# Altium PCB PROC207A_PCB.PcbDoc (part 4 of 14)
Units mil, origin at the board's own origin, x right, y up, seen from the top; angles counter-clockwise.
Board outline 4094.49 x 3724.79 mil, 8 copper layers (Top Layer, L2_GND1, L3_SIG1, L4_PWR1, L5_PWR2, L6_SIG2, L7_GND2, Bottom Layer), stack 58.1 mil thick; 584 components, 399 nets, 8440 pads, 5258 vias.
Unrouted connection lines stored in the file: 9.
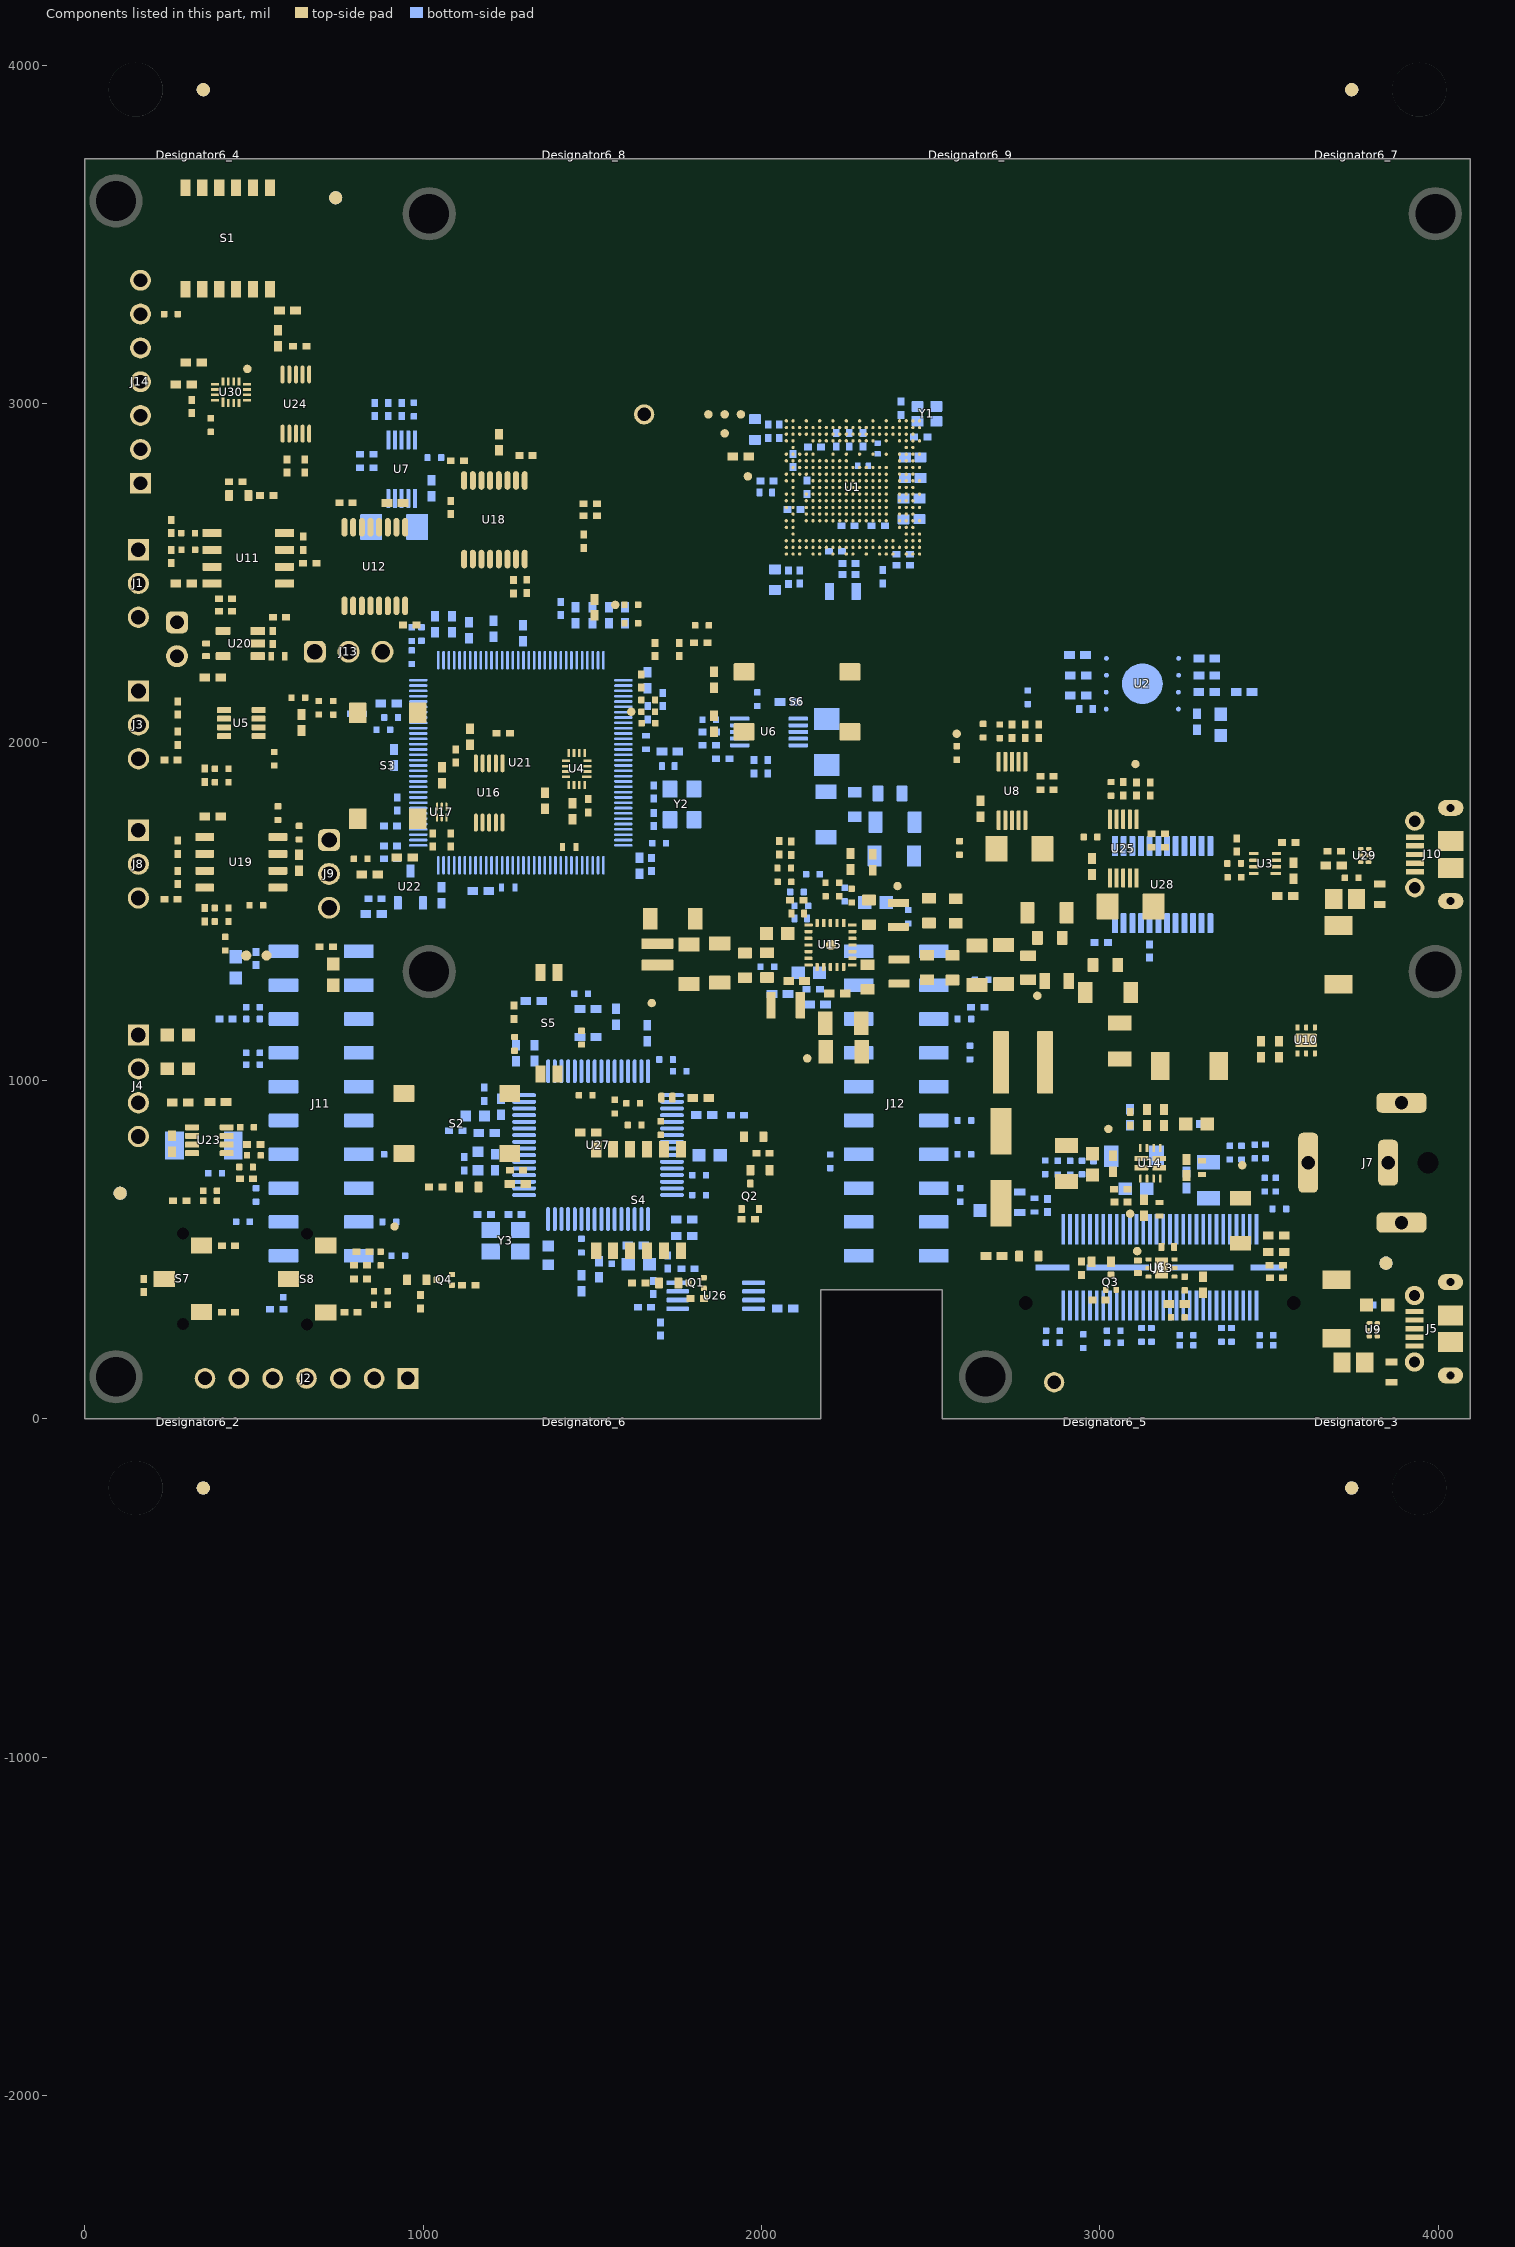
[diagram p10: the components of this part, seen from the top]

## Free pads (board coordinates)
  round 1 on Mech13: 0(1166.41,3201.26)
  round 10 on Mech16: 1(279.42,-2261) 1(279.42,-2261) 1(279.42,3039) 1(279.42,3039) 1(726.33,318.51) 1(740.31,318.51) 1(2054.9,976.3) 1(2066.33,976.3) 1(2509,314.72) 1(2525.34,314.72) 1(2695.25,961) 1(2707.26,961) 1(2839.79,1070.45) 1(2839.79,1745.45) 1(2849.98,1070.45) 1(2849.98,1745.45) 1(3035.32,-2261) 1(3035.32,-2261) 1(3035.32,3039) 1(3035.32,3039) 1(3035.49,821.54) 1(3035.49,1215.24) 1(3035.49,1496.54) 1(3035.49,1890.24)
  round 7.87 on Mech16: 1(316.04,-124.6) 1(316.69,-99.37) 1(319.14,2898.86) 1(319.79,2924.1) 1(331.77,-168.17) 1(332.54,-59.62) 1(334.86,2855.3) 1(335.64,2963.84) 1(343.86,-182.93) 1(346.96,2840.54) 1(349.31,-40.97) 1(352.41,2982.5) 1(381.7,-206.31) 1(381.7,-22.63) 1(384.8,2817.15) 1(384.8,3000.84) 1(397.96,-18.73) 1(401.06,3004.74) 1(406.95,-211.13) 1(410.05,2812.34) 1(436.96,-20.85) 1(440.05,3002.62) 1(449.89,-203.69) 1(451.64,-26) 1(452.98,2819.77) 1(454.73,2997.46) 1(467.16,-194.25) 1(470.26,2829.22) 1(483.26,-48.59) 1(486.36,2974.87) 1(492.87,-168.17) 1(495.97,2855.3) 1(496.16,-66.06) 1(499.26,2957.4) 1(501.54,-152.04) 1(504.64,2871.43) 1(507.94,-99.37) 1(509.01,-119.3) 1(511.04,2924.1) 1(512.11,2904.16) 1(575.75,-153.03) 1(575.75,-113.66) 1(598.27,432) 1(598.27,432) 1(598.27,446.17) 1(598.27,1417.82) 1(598.27,1432) 1(598.27,1432) 1(606.48,31.99) 1(606.48,146.17) 1(606.48,217.82) 1(606.48,332) 1(606.48,332) 1(607.03,32) 1(650.56,-168.77) 1(650.56,-113.66) 1(706.48,320.97) 1(706.48,320.97) 1(706.48,332) 1(706.48,332) 1(706.48,332) 1(707.03,32) 1(707.03,32) 1(707.03,46.17) 1(746.59,320.97) 1(746.59,320.97) 1(746.59,332) 1(746.59,332) 1(749.46,-61.66) 1(749.46,-53.78) 1(749.46,-163.03) 1(749.46,-143.35) 1(798.27,432) 1(798.27,432) 1(798.27,446.17) 1(798.27,1417.82) 1(798.27,1432) 1(798.27,1432) 1(834.11,-158.11) 1(834.11,-150.24) 1(834.11,-61.66) 1(834.11,-53.78) 1(861.88,23.62) 1(861.88,108.27) 1(868.88,173.68) 1(868.88,258.32) 1(869.75,23.62) 1(869.75,108.27) 1(876.75,173.68) 1(876.75,258.32) 1(901.19,1290.09) 1(901.19,1290.09) 1(901.19,1420.01) 1(901.19,1420.01) 1(945.62,-302.27) 1(945.62,-217.62) 1(949.62,-121.27) 1(949.62,-36.62) 1(951.45,23.62) 1(953.49,-302.27) 1(953.49,-217.62) 1(957.49,-121.27) 1(957.49,-36.62) 1(958.34,108.27) 1(958.45,173.68) 1(965.34,258.32) 1(966.21,108.27) 1(971.13,23.62) 1(973.21,258.32) 1(978.13,173.68) 1(987.8,1290.09) 1(987.8,1420.01) 1(1035.19,-302.27) 1(1039.19,-121.27) 1(1042.08,-217.62) 1(1046.08,-36.62) 1(1049.95,-217.62) 1(1053.95,-36.62) 1(1054.87,-302.27) 1(1058.87,-121.27) 1(1063.38,858.87) 1(1063.38,878.56) 1(1063.38,878.56) 1(1082.75,536.38) 1(1082.75,578.71) 1(1083.77,1290.09) 1(1083.77,1420.01) 1(1094.88,878.56) 1(1150,878.56) 1(1170.39,1290.09) 1(1170.39,1290.09) 1(1170.39,1420.01) 1(1170.39,1420.01) 1(1181.49,858.87) 1(1181.49,878.56) 1(1181.49,878.56) 1(1202.83,496.03) 1(1202.83,578.71) 1(1217.33,-293.68) 1(1222.25,-378.33) 1(1230.12,-378.33) 1(1237.01,-293.68) 1(1318.71,-378.33) 1(1318.71,-293.68) 1(1326.58,-378.33) 1(1326.58,-293.68) 1(1353.98,764.89) 1(1353.98,780.64) 1(1353.98,796.38) 1(1353.98,812.13) 1(1353.98,827.88) 1(1353.98,843.63) 1(1353.98,859.38) 1(1353.98,875.12) 1(1353.98,890.87) 1(1353.98,906.62) 1(1353.98,922.37) 1(1353.98,938.12) 1(1353.98,953.86) 1(1353.98,969.61) 1(1353.98,985.36) 1(1353.98,1001.11) 1(1353.98,1016.86) 1(1353.98,1032.6) 1(1353.98,1048.35) 1(1353.98,1064.1) 1(1353.98,1079.85) 1(1353.98,1095.6) 1(1353.98,1111.34) 1(1353.98,1127.09) 1(1353.98,1142.84) 1(1353.98,1158.59) 1(1353.98,1174.34) 1(1353.98,1190.08) 1(1353.98,1205.83) 1(1353.98,1221.58) 1(1353.98,1237.33) 1(1353.98,1253.08) 1(1401.22,764.89) 1(1401.22,780.64) 1(1401.22,796.38) 1(1401.22,812.13) 1(1401.22,827.88) 1(1401.22,843.63) 1(1401.22,859.38) 1(1401.22,875.12) 1(1401.22,890.87) 1(1401.22,906.62) 1(1401.22,922.37) 1(1401.22,938.12) 1(1401.22,953.86) 1(1401.22,969.61) 1(1401.22,985.36) 1(1401.22,1001.11) 1(1401.22,1016.86) 1(1401.22,1032.6) 1(1401.22,1048.35) 1(1401.22,1064.1) 1(1401.22,1079.85) 1(1401.22,1095.6) 1(1401.22,1111.34) 1(1401.22,1127.09) 1(1401.22,1142.84) 1(1401.22,1158.59) 1(1401.22,1174.34) 1(1401.22,1190.08) 1(1401.22,1205.83) 1(1401.22,1221.58) 1(1401.22,1237.33) 1(1401.22,1253.08) 1(1432.72,760.95) 1(1432.72,760.95) 1(1432.72,1257.01) 1(1432.72,1257.01) 1(1436.66,682.21) 1(1436.66,729.45) 1(1436.66,1288.51) 1(1436.66,1335.75) 1(1452.41,682.21) 1(1452.41,729.45) 1(1452.41,1288.51) 1(1452.41,1335.75) 1(1468.15,682.21) 1(1468.15,729.45) 1(1468.15,1288.51) 1(1468.15,1335.75) 1(1483.9,682.21) 1(1483.9,729.45) 1(1483.9,1288.51) 1(1483.9,1335.75) 1(1499.65,682.21) 1(1499.65,729.45) 1(1499.65,1288.51) 1(1499.65,1335.75) 1(1515.4,682.21) 1(1515.4,729.45) 1(1515.4,1288.51) 1(1515.4,1335.75) 1(1531.15,682.21) 1(1531.15,729.45) 1(1531.15,1288.51) 1(1531.15,1335.75) 1(1546.89,682.21) 1(1546.89,729.45) 1(1546.89,1288.51) 1(1546.89,1335.75) 1(1562.64,682.21) 1(1562.64,729.45) 1(1562.64,1288.51) 1(1562.64,1335.75) 1(1575.84,-377.87) 1(1575.84,-369.99) 1(1575.84,-281.41) 1(1575.84,-273.54) 1(1578.39,682.21) 1(1578.39,729.45) 1(1578.39,1288.51) 1(1578.39,1335.75) 1(1594.14,682.21) 1(1594.14,729.45) 1(1594.14,1288.51) 1(1594.14,1335.75) 1(1609.89,682.21) 1(1609.89,729.45) 1(1609.89,1288.51) 1(1609.89,1335.75) 1(1625.63,682.21) 1(1625.63,729.45) 1(1625.63,1288.51) 1(1625.63,1335.75) 1(1641.38,682.21) 1(1641.38,729.45) 1(1641.38,1288.51) 1(1641.38,1335.75) 1(1657.13,682.21) 1(1657.13,729.45) 1(1657.13,1288.51) 1(1657.13,1335.75) 1(1660.49,-288.3) 1(1660.49,-268.62) 1(1660.49,-377.87) 1(1660.49,-369.99) 1(1672.88,682.21) 1(1672.88,729.45) 1(1672.88,1288.51) 1(1672.88,1335.75) 1(1688.63,682.21) 1(1688.63,729.45) 1(1688.63,1288.51) 1(1688.63,1335.75) 1(1704.37,682.21) 1(1704.37,729.45) 1(1704.37,1288.51) 1(1704.37,1335.75) 1(1720.12,682.21) 1(1720.12,729.45) 1(1720.12,1288.51) 1(1720.12,1335.75) 1(1735.87,682.21) 1(1735.87,729.45) 1(1735.87,1288.51) 1(1735.87,1335.75) 1(1751.62,682.21) 1(1751.62,729.45) 1(1751.62,1288.51) 1(1751.62,1335.75) 1(1767.37,682.21) 1(1767.37,729.45) 1(1767.37,1288.51) 1(1767.37,1335.75) 1(1783.11,682.21) 1(1783.11,729.45) 1(1783.11,1288.51) 1(1783.11,1335.75) 1(1798.86,682.21) 1(1798.86,729.45) 1(1798.86,1288.51) 1(1798.86,1335.75) 1(1814.61,682.21) 1(1814.61,729.45) 1(1814.61,1288.51) 1(1814.61,1335.75) 1(1830.36,682.21) 1(1830.36,729.45) 1(1830.36,1288.51) 1(1830.36,1335.75) 1(1846.11,682.21) 1(1846.11,729.45) 1(1846.11,1288.51) 1(1846.11,1335.75) 1(1861.85,682.21) 1(1861.85,729.45) 1(1861.85,1288.51) 1(1861.85,1335.75) 1(1877.6,682.21) 1(1877.6,729.45) 1(1877.6,1288.51) 1(1877.6,1335.75) 1(1893.35,682.21) 1(1893.35,729.45) 1(1893.35,1288.51) 1(1893.35,1335.75) 1(1909.1,682.21) 1(1909.1,729.45) 1(1909.1,1288.51) 1(1909.1,1335.75) 1(1924.85,682.21) 1(1924.85,729.45) 1(1924.85,1288.51) 1(1924.85,1335.75) 1(1928.78,760.95) 1(1928.78,760.95) 1(1928.78,1257.01) 1(1928.78,1257.01) 1(1944.18,289.67) 1(1960.07,447.39) 1(1960.07,447.39) 1(1960.07,569.44) 1(1960.07,569.44) 1(1960.28,764.89) 1(1960.28,780.64) 1(1960.28,796.38) 1(1960.28,812.13) 1(1960.28,827.88) 1(1960.28,843.63) 1(1960.28,859.38) 1(1960.28,875.12) 1(1960.28,890.87) 1(1960.28,906.62) 1(1960.28,922.37) 1(1960.28,938.12) 1(1960.28,953.86) 1(1960.28,969.61) 1(1960.28,985.36) 1(1960.28,1001.11) 1(1960.28,1016.86) 1(1960.28,1032.6) 1(1960.28,1048.35) 1(1960.28,1064.1) 1(1960.28,1079.85) 1(1960.28,1095.6) 1(1960.28,1111.34) 1(1960.28,1127.09) 1(1960.28,1142.84) 1(1960.28,1158.59) 1(1960.28,1174.34) 1(1960.28,1190.08) 1(1960.28,1205.83) 1(1960.28,1221.58) 1(1960.28,1237.33) 1(1960.28,1253.08) 1(2002.49,-846.56) 1(2007.52,764.89) 1(2007.52,780.64) 1(2007.52,796.38) 1(2007.52,812.13) 1(2007.52,827.88) 1(2007.52,843.63) 1(2007.52,859.38) 1(2007.52,875.12) 1(2007.52,890.87) 1(2007.52,906.62) 1(2007.52,922.37) 1(2007.52,938.12) 1(2007.52,953.86) 1(2007.52,969.61) 1(2007.52,985.36) 1(2007.52,1001.11) 1(2007.52,1016.86) 1(2007.52,1032.6) 1(2007.52,1048.35) 1(2007.52,1064.1) 1(2007.52,1079.85) 1(2007.52,1095.6) 1(2007.52,1111.34) 1(2007.52,1127.09) 1(2007.52,1142.84) 1(2007.52,1158.59) 1(2007.52,1174.34) 1(2007.52,1190.08) 1(2007.52,1205.83) 1(2007.52,1221.58) 1(2007.52,1237.33) 1(2007.52,1253.08) 1(2013.08,411.71) 1(2042.61,-337.21) 1(2042.61,-337.21) 1(2042.61,-308.66) 1(2042.61,-134.45) 1(2042.61,-124.61) 1(2042.61,-124.61) 1(2052.45,-124.61) 1(2071.16,-337.21) 1(2071.38,-724.51) 1(2083.94,289.67) 1(2083.94,411.71) 1(2086.06,447.39) 1(2086.06,447.39) 1(2086.06,569.44) 1(2086.06,569.44) 1(2099.79,1190.55) 1(2099.79,1190.55) 1(2099.79,1268.05) 1(2099.79,1268.05) 1(2099.79,1288.05) 1(2099.79,1288.05) 1(2099.79,1368.05) 1(2099.79,1368.05) 1(2099.79,1388.05) 1(2099.79,1388.05) 1(2099.79,1465.55) 1(2099.79,1465.55) 1(2109.29,1178.05) 1(2109.29,1178.05) 1(2109.29,1478.05) 1(2109.29,1478.05) 1(2109.79,1278.05) 1(2109.79,1278.05) 1(2109.79,1378.05) 1(2109.79,1378.05) 1(2112.79,1178.05) 1(2112.79,1478.05) 1(2112.79,1478.05) 1(2142.25,-846.56) 1(2142.25,-724.51) 1(2184.79,1178.05) 1(2184.79,1478.05) 1(2184.79,1478.05) 1(2187.79,1278.05) 1(2187.79,1278.05) 1(2187.79,1378.05) 1(2187.79,1378.05) 1(2188.29,1178.05) 1(2188.29,1178.05) 1(2188.29,1478.05) 1(2188.29,1478.05) 1(2197.79,1190.55) 1(2197.79,1190.55) 1(2197.79,1268.05) 1(2197.79,1268.05) 1(2197.79,1288.05) 1(2197.79,1288.05) 1(2197.79,1368.05) 1(2197.79,1368.05) 1(2197.79,1388.05) 1(2197.79,1388.05) 1(2197.79,1465.55) 1(2197.79,1465.55) 1(2225.68,-337.21) 1(2225.68,-124.61) 1(2235.53,-337.21) 1(2235.53,-337.21) 1(2235.53,-327.36) 1(2235.53,-134.45) 1(2235.53,-124.61) 1(2235.53,-124.61) 1(2298.27,432) 1(2298.27,432) 1(2298.27,446.17) 1(2298.27,1417.82) 1(2298.27,1432) 1(2298.27,1432) 1(2388.96,31.99) 1(2388.96,146.17) 1(2388.96,217.82) 1(2388.96,332) 1(2388.96,332) 1(2389.51,32) 1(2474.25,-297.6) 1(2474.25,-289.72) 1(2474.25,-398.98) 1(2474.25,-379.29) 1(2488.96,320.97) 1(2488.96,320.97) 1(2488.96,332) 1(2488.96,332) 1(2488.96,332) 1(2489.51,32) 1(2489.51,32) 1(2489.51,46.17) 1(2498.27,432) 1(2498.27,432) 1(2498.27,446.17) 1(2498.27,1417.82) 1(2498.27,1432) 1(2498.27,1432) 1(2529.07,320.97) 1(2529.07,320.97) 1(2529.07,332) 1(2529.07,332) 1(2531.35,-629.97) 1(2531.35,-507.92) 1(2537.46,-1844.6) 1(2537.46,-1844.6) 1(2537.46,-1757.99) 1(2537.46,-1662.02) 1(2537.46,-1575.4) 1(2537.46,-1575.4) 1(2548.14,2918.86) 1(2548.79,2944.1) 1(2556.04,-124.6) 1(2556.69,-99.37) 1(2558.89,-394.06) 1(2558.89,-386.18) 1(2558.89,-297.6) 1(2558.89,-289.72) 1(2563.86,2875.3) 1(2564.64,2983.84) 1(2571.77,-168.17) 1(2572.54,-59.62) 1(2575.96,2860.54) 1(2581.41,3002.5) 1(2583.86,-182.93) 1(2589.31,-40.97) 1(2602.22,-629.97) 1(2612.79,575.55) 1(2612.79,575.55) 1(2612.79,653.05) 1(2612.79,653.05) 1(2612.79,673.05) 1(2612.79,673.05) 1(2612.79,753.05) 1(2612.79,753.05) 1(2612.79,773.05) 1(2612.79,773.05) 1(2612.79,850.55) 1(2612.79,850.55) 1(2613.8,2837.15) 1(2613.8,3020.84) 1(2621.7,-206.31) 1(2621.7,-22.63) 1(2622.29,563.05) 1(2622.29,563.05) 1(2622.29,863.05) 1(2622.29,863.05) 1(2622.79,663.05) 1(2622.79,663.05) 1(2622.79,763.05) 1(2622.79,763.05) 1(2625.79,563.05) 1(2625.79,563.05) 1(2625.79,863.05) 1(2630.06,3024.74) 1(2637.96,-18.73) 1(2639.05,2832.34) 1(2646.95,-211.13) 1(2667.38,-1844.6) 1(2667.38,-1844.6) 1(2667.38,-1757.99) 1(2667.38,-1662.02) 1(2667.38,-1575.4) 1(2667.38,-1575.4) 1(2669.05,3022.62) 1(2671.12,-507.92) 1(2676.95,-20.85) 1(2681.98,2839.77) 1(2683.73,3017.46) 1(2689.89,-203.69) 1(2691.64,-26) 1(2697.79,563.05) 1(2697.79,563.05) 1(2697.79,863.05) 1(2699.26,2849.22) 1(2700.79,663.05) 1(2700.79,663.05) 1(2700.79,763.05) 1(2700.79,763.05) 1(2701.29,563.05) 1(2701.29,563.05) 1(2701.29,863.05) 1(2701.29,863.05) 1(2701.73,989.53) 1(2707.16,-194.25) 1(2710.79,575.55) 1(2710.79,575.55) 1(2710.79,653.05) 1(2710.79,653.05) 1(2710.79,673.05) 1(2710.79,673.05) 1(2710.79,753.05) 1(2710.79,753.05) 1(2710.79,773.05) 1(2710.79,773.05) 1(2710.79,850.55) 1(2710.79,850.55) 1(2713.54,1056.46) 1(2715.36,2994.87) 1(2723.26,-48.59) 1(2724.97,2875.3) 1(2728.26,2977.4) 1(2729.29,989.53) 1(2729.29,1056.46) 1(2732.87,-168.17) 1(2733.64,2891.43) 1(2736.16,-66.06) 1(2740.04,2944.1) 1(2741.11,2924.16) 1(2741.54,-152.04) 1(2747.94,-99.37) 1(2749.01,-119.3)
  round 7 on Mech16: 1(374.42,-995.5) 1(374.42,-995.5) 1(374.42,-954.5) 1(374.42,-954.5) 1(374.99,-945.51) 1(374.99,-945.51) 1(374.99,-904.51) 1(374.99,-904.51) 1(374.99,-847.08) 1(374.99,-847.08) 1(374.99,-806.08) 1(374.99,-806.08) 1(375.04,-896.97) 1(375.04,-896.97) 1(375.04,-855.97) 1(375.04,-855.97) 1(376.04,-1047.97) 1(376.04,-1047.97) 1(376.04,-1006.97) 1(376.04,-1006.97) 1(391.42,896.5) 1(391.42,896.5) 1(391.42,937.5) 1(391.42,937.5) 1(391.42,945.5) 1(391.42,945.5) 1(391.42,986.5) 1(391.42,986.5) 1(391.42,847.5) 1(391.42,847.5) 1(391.42,888.5) 1(391.42,888.5) 1(397.42,-995.5) 1(397.42,-954.5) 1(397.99,-945.51) 1(397.99,-904.51) 1(397.99,-847.08) 1(397.99,-806.08) 1(398.04,-896.97) 1(398.04,-855.97) 1(399.04,-1047.97) 1(399.04,-1006.97) 1(414.42,896.5) 1(414.42,937.5) 1(414.42,945.5) 1(414.42,986.5) 1(414.42,847.5) 1(414.42,888.5) 1(447.42,-995.5) 1(447.42,-954.5) 1(447.99,-945.51) 1(447.99,-904.51) 1(447.99,-847.08) 1(447.99,-806.08) 1(448.04,-896.97) 1(448.04,-855.97) 1(449.04,-1047.97) 1(449.04,-1006.97) 1(464.42,896.5) 1(464.42,937.5) 1(464.42,945.5) 1(464.42,986.5) 1(464.42,847.5) 1(464.42,888.5) 1(470.42,-995.5) 1(470.42,-995.5) 1(470.42,-954.5) 1(470.42,-954.5) 1(470.99,-945.51) 1(470.99,-945.51) 1(470.99,-904.51) 1(470.99,-904.51) 1(470.99,-847.08) 1(470.99,-847.08) 1(470.99,-806.08) 1(470.99,-806.08) 1(471.04,-896.97) 1(471.04,-896.97) 1(471.04,-855.97) 1(471.04,-855.97) 1(472.04,-1047.97) 1(472.04,-1047.97) 1(472.04,-1006.97) 1(472.04,-1006.97) 1(487.42,896.5) 1(487.42,896.5) 1(487.42,937.5) 1(487.42,937.5) 1(487.42,945.5) 1(487.42,945.5) 1(487.42,986.5) 1(487.42,986.5) 1(487.42,847.5) 1(487.42,847.5) 1(487.42,888.5) 1(487.42,888.5) 1(593.04,-1018.97) 1(593.04,-1018.97) 1(593.04,-977.97) 1(593.04,-977.97) 1(594.04,-691.97) 1(594.04,-691.97) 1(594.04,-650.97) 1(594.04,-650.97) 1(594.04,-640.97) 1(594.04,-640.97) 1(594.04,-599.97) 1(594.04,-599.97) 1(594.54,-968.47) 1(594.54,-968.47) 1(594.54,-945.47) 1(594.54,-895.47) 1(594.54,-872.47) 1(594.54,-872.47) 1(595.04,-538.97) 1(595.04,-538.97) 1(595.04,-497.97) 1(595.04,-497.97) 1(595.29,-589.97) 1(595.29,-589.97) 1(595.29,-548.97) 1(595.29,-548.97) 1(596.04,-487.97) 1(596.04,-487.97) 1(596.04,-446.97) 1(596.04,-446.97) 1(616.04,-1018.97) 1(616.04,-977.97) 1(617.04,-691.97) 1(617.04,-650.97) 1(617.04,-640.97) 1(617.04,-599.97) 1(618.04,-538.97) 1(618.04,-497.97) 1(618.29,-589.97) 1(618.29,-548.97) 1(619.04,-487.97) 1(619.04,-446.97) 1(635.54,-968.47) 1(635.54,-968.47) 1(635.54,-945.47) 1(635.54,-895.47) 1(635.54,-872.47) 1(635.54,-872.47) 1(645.54,-968.47) 1(645.54,-968.47) 1(645.54,-945.47) 1(645.54,-895.47) 1(645.54,-872.47) 1(645.54,-872.47) 1(666.04,-1018.97) 1(666.04,-977.97) 1(667.04,-691.97) 1(667.04,-650.97) 1(667.04,-640.97) 1(667.04,-599.97) 1(668.04,-538.97) 1(668.04,-497.97) 1(668.29,-589.97) 1(668.29,-548.97) 1(669.04,-487.97) 1(669.04,-446.97) 1(686.54,-968.47) 1(686.54,-968.47) 1(686.54,-945.47) 1(686.54,-895.47) 1(686.54,-872.47) 1(686.54,-872.47) 1(689.04,-1018.97) 1(689.04,-1018.97) 1(689.04,-977.97) 1(689.04,-977.97) 1(690.04,-691.97) 1(690.04,-691.97) 1(690.04,-650.97) 1(690.04,-650.97) 1(690.04,-640.97) 1(690.04,-640.97) 1(690.04,-599.97) 1(690.04,-599.97) 1(691.04,-538.97) 1(691.04,-538.97) 1(691.04,-497.97) 1(691.04,-497.97) 1(691.29,-589.97) 1(691.29,-589.97) 1(691.29,-548.97) 1(691.29,-548.97) 1(692.04,-487.97) 1(692.04,-487.97) 1(692.04,-446.97) 1(692.04,-446.97) 1(751.15,-607.43) 1(751.15,-607.43) 1(751.15,-572) 1(751.15,-453.89) 1(751.15,-418.46) 1(751.15,-418.46) 1(788.55,2168.57) 1(788.55,2168.57) 1(788.55,2204) 1(788.55,2322.11) 1(788.55,2357.54) 1(788.55,2357.54) 1(796.12,-1377.28) 1(796.12,-1377.28) 1(796.12,-1336.28) 1(796.12,-1336.28) 1(796.12,-1301.41) 1(796.12,-1301.41) 1(796.12,-1260.41) 1(796.12,-1260.41) 1(796.3,-1119.58) 1(796.3,-1119.58) 1(796.3,-1024.31) 1(796.3,-1024.31) 1(798.29,-406.95) 1(798.29,-406.95) 1(798.29,-383.95) 1(798.29,-333.95) 1(798.29,-310.95) 1(798.29,-310.95) 1(819.12,-1377.28) 1(819.12,-1336.28) 1(819.12,-1301.41) 1(819.12,-1260.41) 1(821.15,-1251.98) 1(821.15,-1251.98) 1(821.15,-1226) 1(821.15,-1158) 1(821.15,-1132.02) 1(821.15,-1132.02) 1(825.92,-1536) 1(825.92,-1536) 1(825.92,-1513) 1(825.92,-1463) 1(825.92,-1440) 1(825.92,-1440) 1(831.73,-1119.58) 1(831.73,-1024.31) 1(839.29,-406.95) 1(839.29,-406.95) 1(839.29,-383.95) 1(839.29,-333.95) 1(839.29,-310.95) 1(839.29,-310.95) 1(846.42,-607.43) 1(846.42,-607.43) 1(846.42,-572) 1(846.42,-453.89) 1(846.42,-418.46) 1(846.42,-418.46) 1(866.92,-1536) 1(866.92,-1536) 1(866.92,-1513) 1(866.92,-1463) 1(866.92,-1440) 1(866.92,-1440) 1(869.12,-1377.28) 1(869.12,-1336.28) 1(869.12,-1301.41) 1(869.12,-1260.41) 1(875.62,-1251.98) 1(875.62,-1251.98) 1(875.62,-1226) 1(875.62,-1158) 1(875.62,-1132.02) 1(875.62,-1132.02) 1(875.92,-1536) 1(875.92,-1536) 1(875.92,-1513) 1(875.92,-1463) 1(875.92,-1440) 1(875.92,-1440) 1(883.83,2168.57) 1(883.83,2168.57) 1(883.83,2204) 1(883.83,2322.11) 1(883.83,2357.54) 1(883.83,2357.54) 1(892.12,-1377.28) 1(892.12,-1377.28) 1(892.12,-1336.28) 1(892.12,-1336.28) 1(892.12,-1301.41) 1(892.12,-1301.41) 1(892.12,-1260.41) 1(892.12,-1260.41) 1(916.92,-1536) 1(916.92,-1536) 1(916.92,-1513) 1(916.92,-1463) 1(916.92,-1440) 1(916.92,-1440) 1(922.04,-1184.97) 1(922.04,-1184.97) 1(922.04,-1143.97) 1(922.04,-1143.97) 1(925.79,-1370.5) 1(925.79,-1370.5) 1(925.79,-1329.5) 1(925.79,-1329.5) 1(927.11,-1537.35) 1(927.11,-1537.35) 1(927.11,-1514.35) 1(927.11,-1464.35) 1(927.11,-1441.35) 1(927.11,-1441.35) 1(930.79,-1280.5) 1(930.79,-1280.5) 1(930.79,-1239.5) 1(930.79,-1239.5) 1(945.04,-1184.97) 1(945.04,-1143.97) 1(948.79,-1370.5) 1(948.79,-1329.5) 1(949.84,-1119.58) 1(949.84,-1024.31) 1(953.79,-1280.5) 1(953.79,-1239.5) 1(968.11,-1537.35) 1(968.11,-1537.35) 1(968.11,-1514.35) 1(968.11,-1464.35) 1(968.11,-1441.35) 1(968.11,-1441.35) 1(969.41,-466.45) 1(969.41,-466.45) 1(969.41,-425.45) 1(969.41,-425.45) 1(978.79,-756.45) 1(978.79,-756.45) 1(978.79,-715.45) 1(978.79,-715.45) 1(979.79,-582.45) 1(979.79,-582.45) 1(979.79,-541.45) 1(979.79,-541.45) 1(980.16,-673.45) 1(980.16,-673.45) 1(980.16,-632.45) 1(980.16,-632.45) 1(982.11,-1537.35) 1(982.11,-1537.35) 1(982.11,-1514.35) 1(982.11,-1464.35) 1(982.11,-1441.35) 1(982.11,-1441.35) 1(985.27,-1119.58) 1(985.27,-1119.58) 1(985.27,-1024.31) 1(985.27,-1024.31) 1(992.41,-466.45) 1(992.41,-425.45) 1(995.04,-1184.97) 1(995.04,-1143.97) 1(998.79,-1370.5) 1(998.79,-1329.5) 1(1001.79,-756.45) 1(1001.79,-715.45) 1(1002.79,-582.45) 1(1002.79,-541.45) 1(1003.15,960.56) 1(1003.15,960.56) 1(1003.15,996) 1(1003.15,1114.11) 1(1003.15,1149.54) 1(1003.15,1149.54) 1(1003.16,-673.45) 1(1003.16,-632.45) 1(1003.79,-1280.5) 1(1003.79,-1239.5) 1(1015.05,242.5) 1(1015.05,242.5) 1(1015.05,283.5) 1(1015.05,283.5) 1(1018.04,-1184.97) 1(1018.04,-1184.97) 1(1018.04,-1143.97) 1(1018.04,-1143.97) 1(1021.42,2141.84) 1(1021.42,2141.84) 1(1021.42,2182.84) 1(1021.42,2182.84) 1(1021.42,2191.84) 1(1021.42,2191.84) 1(1021.42,2232.84) 1(1021.42,2232.84) 1(1021.42,2291.84) 1(1021.42,2291.84) 1(1021.42,2332.84) 1(1021.42,2332.84) 1(1021.42,2241.84) 1(1021.42,2241.84) 1(1021.42,2282.84) 1(1021.42,2282.84) 1(1021.79,-1370.5) 1(1021.79,-1370.5) 1(1021.79,-1329.5) 1(1021.79,-1329.5) 1(1023.11,-1537.35) 1(1023.11,-1537.35) 1(1023.11,-1514.35) 1(1023.11,-1464.35) 1(1023.11,-1441.35) 1(1023.11,-1441.35) 1(1026.79,-1280.5) 1(1026.79,-1280.5) 1(1026.79,-1239.5) 1(1026.79,-1239.5) 1(1038.05,242.5) 1(1038.05,283.5) 1(1039.68,118.44) 1(1039.68,118.44) 1(1039.68,159.44) 1(1039.68,159.44) 1(1042.41,-466.45) 1(1042.41,-425.45) 1(1044.42,2141.84) 1(1044.42,2182.84) 1(1044.42,2191.84) 1(1044.42,2232.84) 1(1044.42,2291.84) 1(1044.42,2332.84) 1(1044.42,2241.84) 1(1044.42,2282.84) 1(1048.29,-1539.95) 1(1048.29,-1539.95) 1(1048.29,-1516.95) 1(1048.29,-1466.95) 1(1048.29,-1443.95) 1(1048.29,-1443.95) 1(1051.79,-756.45) 1(1051.79,-715.45) 1(1052.79,-582.45) 1(1052.79,-541.45) 1(1053.16,-673.45) 1(1053.16,-632.45) 1(1062.68,118.44) 1(1062.68,159.44) 1(1065.41,-466.45) 1(1065.41,-466.45) 1(1065.41,-425.45) 1(1065.41,-425.45) 1(1066.02,670.6) 1(1066.02,743.6) 1(1066.02,743.6) 1(1066.02,647.6) 1(1066.02,647.6) 1(1066.02,720.6) 1(1074.79,-756.45) 1(1074.79,-756.45) 1(1074.79,-715.45) 1(1074.79,-715.45) 1(1075.79,-582.45) 1(1075.79,-582.45) 1(1075.79,-541.45) 1(1075.79,-541.45) 1(1076.16,-673.45) 1(1076.16,-673.45) 1(1076.16,-632.45) 1(1076.16,-632.45) 1(1078.92,366) 1(1078.92,366) 1(1078.92,389) 1(1078.92,439) 1(1078.92,462) 1(1078.92,462) 1(1081.16,-391.45) 1(1081.16,-391.45) 1(1081.16,-350.45) 1(1081.16,-350.45) 1(1088.05,242.5) 1(1088.05,283.5) 1(1089.29,-1539.95) 1(1089.29,-1539.95) 1(1089.29,-1516.95) 1(1089.29,-1466.95) 1(1089.29,-1443.95) 1(1089.29,-1443.95) 1(1094.42,2141.84) 1(1094.42,2182.84) 1(1094.42,2191.84) 1(1094.42,2232.84) 1(1094.42,2291.84) 1(1094.42,2332.84) 1(1094.42,2241.84) 1(1094.42,2282.84) 1(1098.42,960.56) 1(1098.42,960.56) 1(1098.42,996) 1(1098.42,1114.11) 1(1098.42,1149.54) 1(1098.42,1149.54) 1(1104.16,-391.45) 1(1104.16,-350.45) 1(1107.02,647.6) 1(1107.02,647.6) 1(1107.02,720.6) 1(1107.02,670.6) 1(1107.02,743.6) 1(1107.02,743.6) 1(1108.29,-1539.95) 1(1108.29,-1539.95) 1(1108.29,-1516.95) 1(1108.29,-1466.95) 1(1108.29,-1443.95) 1(1108.29,-1443.95) 1(1111.05,242.5) 1(1111.05,242.5) 1(1111.05,283.5) 1(1111.05,283.5) 1(1112.68,118.44) 1(1112.68,159.44) 1(1115.02,647.8) 1(1115.02,647.8) 1(1115.02,670.8) 1(1115.02,720.8) 1(1115.02,743.8) 1(1115.02,743.8) 1(1117.42,2141.84) 1(1117.42,2141.84) 1(1117.42,2182.84) 1(1117.42,2182.84) 1(1117.42,2191.84) 1(1117.42,2191.84) 1(1117.42,2232.84) 1(1117.42,2232.84) 1(1117.42,2291.84) 1(1117.42,2291.84) 1(1117.42,2332.84) 1(1117.42,2332.84) 1(1117.42,2241.84) 1(1117.42,2241.84) 1(1117.42,2282.84) 1(1117.42,2282.84) 1(1119.92,366) 1(1119.92,366) 1(1119.92,389) 1(1119.92,439) 1(1119.92,462) 1(1119.92,462) 1(1135.68,118.44) 1(1135.68,118.44) 1(1135.68,159.44) 1(1135.68,159.44) 1(1144.79,-443.45) 1(1144.79,-443.45) 1(1144.79,-402.45) 1(1144.79,-402.45) 1(1149.29,-1539.95) 1(1149.29,-1539.95) 1(1149.29,-1516.95) 1(1149.29,-1466.95) 1(1149.29,-1443.95) 1(1149.29,-1443.95) 1(1152.52,345.81) 1(1152.52,345.81) 1(1152.52,371.79) 1(1152.52,439.79) 1(1152.52,465.78) 1(1152.52,465.78) 1(1154.16,-391.45) 1(1154.16,-350.45) 1(1156.02,647.8) 1(1156.02,647.8) 1(1156.02,670.8) 1(1156.02,720.8) 1(1156.02,743.8) 1(1156.02,743.8) 1(1164.59,644.02) 1(1164.59,644.02) 1(1164.59,670) 1(1164.59,738) 1(1164.59,763.98) 1(1164.59,763.98) 1(1167.79,-443.45) 1(1167.79,-402.45) 1(1177.16,-391.45) 1(1177.16,-391.45) 1(1177.16,-350.45) 1(1177.16,-350.45) 1(1206.99,345.81) 1(1206.99,345.81) 1(1206.99,371.79) 1(1206.99,439.79) 1(1206.99,465.78) 1(1206.99,465.78) 1(1207.79,1117.55) 1(1207.79,1117.55) 1(1207.79,1158.55) 1(1207.79,1158.55) 1(1208.27,1017.65) 1(1208.27,1017.65) 1(1208.27,1058.65) 1(1208.27,1058.65) 1(1208.29,-1536.32) 1(1208.29,-1536.32) 1(1208.29,-1513.32) 1(1208.29,-1463.32) 1(1208.29,-1440.32) 1(1208.29,-1440.32) 1(1208.79,1067.55) 1(1208.79,1067.55) 1(1208.79,1108.55) 1(1208.79,1108.55) 1(1217.79,-443.45) 1(1217.79,-402.45) 1(1219.05,644.02) 1(1219.05,644.02) 1(1219.05,670) 1(1219.05,738) 1(1219.05,763.98) 1(1219.05,763.98) 1(1230.79,1117.55) 1(1230.79,1158.55) 1(1231.27,1017.65) 1(1231.27,1058.65) 1(1231.79,1067.55) 1(1231.79,1108.55) 1(1240.79,-443.45) 1(1240.79,-443.45) 1(1240.79,-402.45) 1(1240.79,-402.45) 1(1244.52,-620.93) 1(1244.52,-620.93) 1(1244.52,-594.95) 1(1244.52,-526.95) 1(1244.52,-500.96) 1(1244.52,-500.96) 1(1249.29,-1536.32) 1(1249.29,-1536.32) 1(1249.29,-1513.32) 1(1249.29,-1463.32) 1(1249.29,-1440.32) 1(1249.29,-1440.32) 1(1263.29,-1536.32) 1(1263.29,-1536.32) 1(1263.29,-1513.32) 1(1263.29,-1463.32) 1(1263.29,-1440.32) 1(1263.29,-1440.32) 1(1280.79,1117.55) 1(1280.79,1158.55) 1(1281.27,1017.65) 1(1281.27,1058.65) 1(1281.79,1067.55) 1(1281.79,1108.55) 1(1298.99,-620.93) 1(1298.99,-620.93) 1(1298.99,-594.95) 1(1298.99,-526.95) 1(1298.99,-500.96) 1(1298.99,-500.96) 1(1299.79,1341.55) 1(1299.79,1341.55) 1(1299.79,1382.55) 1(1299.79,1382.55) 1(1299.79,1391.55) 1(1299.79,1391.55) 1(1299.79,1432.55) 1(1299.79,1432.55) 1(1303.79,1117.55) 1(1303.79,1117.55) 1(1303.79,1158.55) 1(1303.79,1158.55) 1(1304.27,1017.65) 1(1304.27,1017.65) 1(1304.27,1058.65) 1(1304.27,1058.65) 1(1304.29,-1536.32) 1(1304.29,-1536.32) 1(1304.29,-1513.32) 1(1304.29,-1463.32) 1(1304.29,-1440.32) 1(1304.29,-1440.32) 1(1304.79,1067.55) 1(1304.79,1067.55) 1(1304.79,1108.55) 1(1304.79,1108.55) 1(1316.07,-1537.35) 1(1316.07,-1537.35) 1(1316.07,-1514.35) 1(1316.07,-1464.35) 1(1316.07,-1441.35) 1(1316.07,-1441.35) 1(1322.79,1341.55) 1(1322.79,1382.55) 1(1322.79,1391.55) 1(1322.79,1432.55) 1(1326.56,-522.29) 1(1326.56,-522.29) 1(1326.56,-467.83) 1(1326.56,-467.83) 1(1352.54,-522.29) 1(1352.54,-467.83) 1(1357.07,-1537.35) 1(1357.07,-1537.35) 1(1357.07,-1514.35) 1(1357.07,-1464.35) 1(1357.07,-1441.35) 1(1357.07,-1441.35) 1(1372.79,1341.55) 1(1372.79,1382.55) 1(1372.79,1391.55) 1(1372.79,1432.55) 1(1376.79,-1389.45) 1(1376.79,-1389.45) 1(1376.79,-1348.45) 1(1376.79,-1348.45) 1(1395.79,1341.55) 1(1395.79,1341.55) 1(1395.79,1382.55) 1(1395.79,1382.55) 1(1395.79,1391.55) 1(1395.79,1391.55) 1(1395.79,1432.55) 1(1395.79,1432.55) 1(1397.79,-1544.65) 1(1397.79,-1544.65) 1(1397.79,-1503.65) 1(1397.79,-1503.65) 1(1397.79,-1494.45) 1(1397.79,-1494.45) 1(1397.79,-1453.45) 1(1397.79,-1453.45) 1(1399.79,-1389.45) 1(1399.79,-1348.45) 1(1416.16,487.55) 1(1416.16,487.55) 1(1416.16,528.55) 1(1416.16,528.55) 1(1420.54,-522.29) 1(1420.54,-467.83) 1(1420.79,-1544.65) 1(1420.79,-1503.65) 1(1420.79,-1494.45) 1(1420.79,-1453.45) 1(1433.16,-314.45) 1(1433.16,-314.45) 1(1433.16,-273.45) 1(1433.16,-273.45) 1(1439.16,487.55) 1(1439.16,528.55) 1(1446.53,-522.29) 1(1446.53,-522.29) 1(1446.53,-467.83) 1(1446.53,-467.83) 1(1449.79,-1389.45) 1(1449.79,-1348.45) 1(1456.16,-314.45) 1(1456.16,-273.45) 1(1469.4,1383.38) 1(1469.4,1383.38) 1(1469.4,1406.38) 1(1469.4,1456.38) 1(1469.4,1479.38) 1(1469.4,1479.38) 1(1470.79,-1544.65) 1(1470.79,-1503.65) 1(1470.79,-1494.45) 1(1470.79,-1453.45) 1(1472.79,-1389.45) 1(1472.79,-1389.45) 1(1472.79,-1348.45) 1(1472.79,-1348.45) 1(1478.92,312.38) 1(1478.92,312.38) 1(1478.92,335.38) 1(1478.92,385.38) 1(1478.92,408.38) 1(1478.92,408.38) 1(1489.16,487.55) 1(1489.16,528.55) 1(1493.79,-1544.65) 1(1493.79,-1544.65) 1(1493.79,-1503.65) 1(1493.79,-1503.65) 1(1493.79,-1494.45) 1(1493.79,-1494.45) 1(1493.79,-1453.45) 1(1493.79,-1453.45) 1(1498.23,-737.72) 1(1498.23,-737.72) 1(1498.23,-696.72) 1(1498.23,-696.72) 1(1505.73,-685.22) 1(1505.73,-685.22) 1(1505.73,-662.22) 1(1505.73,-612.22) 1(1505.73,-589.22) 1(1505.73,-589.22) 1(1506.16,-314.45) 1(1506.16,-273.45) 1(1510.4,1383.38) 1(1510.4,1383.38) 1(1510.4,1406.38) 1(1510.4,1456.38) 1(1510.4,1479.38) 1(1510.4,1479.38) 1(1512.16,487.55) 1(1512.16,487.55) 1(1512.16,528.55) 1(1512.16,528.55) 1(1512.79,-227.45) 1(1512.79,-227.45) 1(1512.79,-186.45) 1(1512.79,-186.45) 1(1519.92,312.38) 1(1519.92,312.38) 1(1519.92,335.38) 1(1519.92,385.38) 1(1519.92,408.38) 1(1519.92,408.38) 1(1521.23,-737.72) 1(1521.23,-696.72) 1(1529.16,-314.45) 1(1529.16,-314.45) 1(1529.16,-273.45) 1(1529.16,-273.45) 1(1534.43,342.19) 1(1534.43,342.19) 1(1534.43,365.19) 1(1534.43,415.19) 1(1534.43,438.19) 1(1534.43,438.19) 1(1534.43,447.19) 1(1534.43,447.19) 1(1534.43,470.19) 1(1534.43,520.19) 1(1534.43,543.19) 1(1534.43,543.19) 1(1535.79,-227.45) 1(1535.79,-186.45) 1(1536.41,-1544.65) 1(1536.41,-1544.65) 1(1536.41,-1503.65) 1(1536.41,-1503.65) 1(1541.79,136.55) 1(1541.79,136.55) 1(1541.79,177.55) 1(1541.79,177.55) 1(1546.73,-685.22) 1(1546.73,-685.22) 1(1546.73,-662.22) 1(1546.73,-612.22) 1(1546.73,-589.22) 1(1546.73,-589.22) 1(1559.41,-1544.65) 1(1559.41,-1503.65) 1(1560.73,-685.22) 1(1560.73,-685.22) 1(1560.73,-662.22) 1(1560.73,-612.22) 1(1560.73,-589.22) 1(1560.73,-589.22) 1(1564.79,136.55) 1(1564.79,177.55) 1(1571.23,-737.72) 1(1571.23,-696.72) 1(1575.2,-1497.45) 1(1575.2,-1497.45) 1(1575.2,-1456.45) 1(1575.2,-1456.45) 1(1575.43,342.19) 1(1575.43,342.19) 1(1575.43,365.19) 1(1575.43,415.19) 1(1575.43,438.19) 1(1575.43,438.19) 1(1575.43,447.19) 1(1575.43,447.19) 1(1575.43,470.19) 1(1575.43,520.19) 1(1575.43,543.19) 1(1575.43,543.19) 1(1585.79,-227.45) 1(1585.79,-186.45) 1(1591.42,-61.5) 1(1591.42,-61.5) 1(1591.42,-20.5) 1(1591.42,-20.5) 1(1591.42,3.5) 1(1591.42,3.5) 1(1591.42,44.5) 1(1591.42,44.5) 1(1594.23,-737.72) 1(1594.23,-737.72) 1(1594.23,-696.72) 1(1594.23,-696.72) 1(1598.2,-1497.45) 1(1598.2,-1456.45) 1(1598.77,1360.58) 1(1598.77,1360.58) 1(1598.77,1383.58) 1(1598.77,1433.58) 1(1598.77,1456.58) 1(1598.77,1456.58) 1(1601.73,-685.22) 1(1601.73,-685.22) 1(1601.73,-662.22) 1(1601.73,-612.22) 1(1601.73,-589.22) 1(1601.73,-589.22) 1(1608.79,-227.45) 1(1608.79,-227.45) 1(1608.79,-186.45) 1(1608.79,-186.45) 1(1609.41,-1544.65) 1(1609.41,-1503.65) 1(1614.42,-61.5) 1(1614.42,-20.5) 1(1614.42,3.5) 1(1614.42,44.5) 1(1614.79,136.55) 1(1614.79,177.55) 1(1632.41,-1544.65) 1(1632.41,-1544.65) 1(1632.41,-1503.65) 1(1632.41,-1503.65) 1(1637.79,136.55) 1(1637.79,136.55) 1(1637.79,177.55) 1(1637.79,177.55) 1(1639.77,1360.58) 1(1639.77,1360.58) 1(1639.77,1383.58) 1(1639.77,1433.58) 1(1639.77,1456.58) 1(1639.77,1456.58) 1(1648.2,-1497.45) 1(1648.2,-1456.45) 1(1650.37,-1546.68) 1(1650.37,-1546.68) 1(1650.37,-1505.68) 1(1650.37,-1505.68) 1(1658.92,342.19) 1(1658.92,342.19) 1(1658.92,365.19) 1(1658.92,415.19) 1(1658.92,438.19) 1(1658.92,438.19) 1(1659.19,447.19) 1(1659.19,447.19) 1(1659.19,470.19) 1(1659.19,520.19) 1(1659.19,543.19) 1(1659.19,543.19) 1(1664.42,-61.5) 1(1664.42,-20.5) 1(1664.42,3.5) 1(1664.42,44.5) 1(1671.2,-1497.45) 1(1671.2,-1497.45) 1(1671.2,-1456.45) 1(1671.2,-1456.45) 1(1673.37,-1546.68) 1(1673.37,-1505.68) 1(1680.29,551.05) 1(1680.29,551.05) 1(1680.29,574.05) 1(1680.29,624.05) 1(1680.29,647.05) 1(1680.29,647.05) 1(1681.42,-224.5) 1(1681.42,-224.5) 1(1681.42,-183.5) 1(1681.42,-183.5) 1(1687.01,-151.26) 1(1687.01,-151.26) 1(1687.01,-110.26) 1(1687.01,-110.26) 1(1687.42,-61.5) 1(1687.42,-61.5) 1(1687.42,-20.5) 1(1687.42,-20.5) 1(1687.42,3.5) 1(1687.42,3.5) 1(1687.42,44.5) 1(1687.42,44.5) 1(1688.68,-780.38) 1(1688.68,-780.38) 1(1688.68,-739.38) 1(1688.68,-739.38) 1(1689.58,-682.23) 1(1689.58,-682.23) 1(1689.58,-641.23) 1(1689.58,-641.23) 1(1689.58,-632.23) 1(1689.58,-632.23) 1(1689.58,-591.23) 1(1689.58,-591.23) 1(1689.58,-732.23) 1(1689.58,-732.23) 1(1689.58,-691.23) 1(1689.58,-691.23) 1(1689.58,-582.23) 1(1689.58,-582.23) 1(1689.58,-541.23) 1(1689.58,-541.23) 1(1699.92,342.19) 1(1699.92,342.19) 1(1699.92,365.19) 1(1699.92,415.19) 1(1699.92,438.19) 1(1699.92,438.19) 1(1700.19,447.19) 1(1700.19,447.19) 1(1700.19,470.19) 1(1700.19,520.19) 1(1700.19,543.19) 1(1700.19,543.19) 1(1704.42,-224.5) 1(1704.42,-183.5) 1(1710.01,-151.26) 1(1710.01,-110.26) 1(1711.68,-780.38) 1(1711.68,-739.38) 1(1712.58,-682.23) 1(1712.58,-641.23) 1(1712.58,-632.23) 1(1712.58,-591.23) 1(1712.58,-732.23) 1(1712.58,-691.23) 1(1712.58,-582.23) 1(1712.58,-541.23) 1(1721.29,551.05) 1(1721.29,551.05) 1(1721.29,574.05) 1(1721.29,624.05) 1(1721.29,647.05) 1(1721.29,647.05) 1(1723.37,-1546.68) 1(1723.37,-1505.68) 1(1730.79,593.55) 1(1730.79,593.55) 1(1730.79,634.55) 1(1730.79,634.55) 1(1746.37,-1546.68) 1(1746.37,-1546.68) 1(1746.37,-1505.68) 1(1746.37,-1505.68) 1(1751.35,318.37) 1(1751.35,318.37) 1(1751.35,359.37) 1(1751.35,359.37) 1(1751.46,251.63) 1(1751.46,251.63) 1(1751.46,292.63) 1(1751.46,292.63) 1(1753.79,593.55) 1(1753.79,634.55) 1(1754.42,-224.5) 1(1754.42,-183.5) 1(1760.01,-151.26) 1(1760.01,-110.26) 1(1761.68,-780.38) 1(1761.68,-739.38) 1(1762.58,-682.23) 1(1762.58,-641.23) 1(1762.58,-632.23) 1(1762.58,-591.23) 1(1762.58,-732.23) 1(1762.58,-691.23) 1(1762.58,-582.23) 1(1762.58,-541.23) 1(1774.35,318.37) 1(1774.35,359.37) 1(1774.46,251.63) 1(1774.46,292.63) 1(1777.42,-224.5) 1(1777.42,-224.5) 1(1777.42,-183.5) 1(1777.42,-183.5) 1(1783.01,-151.26) 1(1783.01,-151.26) 1(1783.01,-110.26) 1(1783.01,-110.26) 1(1784.68,-780.38) 1(1784.68,-780.38) 1(1784.68,-739.38) 1(1784.68,-739.38) 1(1785.58,-682.23) 1(1785.58,-682.23) 1(1785.58,-641.23) 1(1785.58,-641.23) 1(1785.58,-632.23) 1(1785.58,-632.23) 1(1785.58,-591.23) 1(1785.58,-591.23) 1(1785.58,-732.23) 1(1785.58,-732.23) 1(1785.58,-691.23) 1(1785.58,-691.23) 1(1785.58,-582.23) 1(1785.58,-582.23) 1(1785.58,-541.23) 1(1785.58,-541.23) 1(1789.26,-1552.45) 1(1789.26,-1552.45) 1(1789.26,-1511.45) 1(1789.26,-1511.45) 1(1795.73,-680.22) 1(1795.73,-680.22) 1(1795.73,-657.22) 1(1795.73,-607.22) 1(1795.73,-584.22) 1(1795.73,-584.22) 1(1803.79,593.55) 1(1803.79,634.55) 1(1812.26,-1552.45) 1(1812.26,-1511.45) 1(1824.35,318.37) 1(1824.35,359.37) 1(1824.46,251.63) 1(1824.46,292.63) 1(1826.79,593.55) 1(1826.79,593.55) 1(1826.79,634.55) 1(1826.79,634.55) 1(1836.73,-680.22) 1(1836.73,-680.22) 1(1836.73,-657.22) 1(1836.73,-607.22) 1(1836.73,-584.22) 1(1836.73,-584.22) 1(1846.19,135.16) 1(1846.19,135.16) 1(1846.19,230.43) 1(1846.19,230.43) 1(1847.35,318.37) 1(1847.35,318.37) 1(1847.35,359.37) 1(1847.35,359.37) 1(1847.46,251.63) 1(1847.46,251.63) 1(1847.46,292.63) 1(1847.46,292.63) 1(1857.01,-702.54) 1(1857.01,-702.54) 1(1857.01,-607.27) 1(1857.01,-607.27) 1(1862.26,-1552.45) 1(1862.26,-1511.45) 1(1881.63,135.16) 1(1881.63,230.43) 1(1885.26,-1552.45) 1(1885.26,-1552.45) 1(1885.26,-1511.45) 1(1885.26,-1511.45) 1(1892.45,-702.54) 1(1892.45,-607.27) 1(1923.04,2164.49) 1(1923.04,2164.49) 1(1923.04,2205.49) 1(1923.04,2205.49) 1(1923.05,2223.5) 1(1923.05,2223.5) 1(1923.05,2264.5) 1(1923.05,2264.5) 1(1946.04,2164.49) 1(1946.04,2205.49) 1(1946.05,2223.5) 1(1946.05,2264.5) 1(1950.42,2377.49) 1(1950.42,2377.49) 1(1950.42,2418.49) 1(1950.42,2418.49) 1(1951.42,2431.49) 1(1951.42,2431.49) 1(1951.42,2472.49) 1(1951.42,2472.49) 1(1952.05,2059.5) 1(1952.05,2059.5) 1(1952.05,2100.5) 1(1952.05,2100.5) 1(1973.42,2377.49) 1(1973.42,2418.49) 1(1974.17,2113.37) 1(1974.17,2113.37) 1(1974.17,2136.37) 1(1974.17,2209.37) 1(1974.17,2219.62) 1(1974.17,2292.62) 1(1974.17,2315.62) 1(1974.17,2315.62) 1(1974.42,2431.49) 1(1974.42,2472.49) 1(1975.05,2059.5) 1(1975.05,2100.5) 1(1990.64,-469.68) 1(1990.64,-469.68) 1(1990.64,-429.68) 1(1990.64,-429.68) 1(1990.64,-389.68) 1(1990.64,-389.68) 1(1990.64,-73.54) 1(1990.64,-73.54) 1(1990.64,-33.54) 1(1990.64,-33.54) 1(1990.64,6.46) 1(1990.64,6.46) 1(1999.74,230.43) 1(2001.54,2326.37) 1(2001.54,2326.37) 1(2001.54,2349.37) 1(2001.54,2422.37) 1(2002.17,2007.38) 1(2002.17,2007.38) 1(2002.17,2030.38) 1(2002.17,2103.38) 1(2010.56,-702.54) 1(2010.56,-607.27) 1(2015.17,2113.37) 1(2015.17,2113.37) 1(2015.17,2136.37) 1(2015.17,2209.37) 1(2015.17,2219.62) 1(2015.17,2292.62) 1(2015.17,2315.62) 1(2015.17,2315.62) 1(2019.04,2164.49) 1(2019.04,2205.49) 1(2019.05,2223.5) 1(2019.05,2264.5) 1(2024.42,2431.49) 1(2024.42,2472.49) 1(2024.64,-469.68) 1(2024.64,-389.68) 1(2024.64,-73.54) 1(2024.64,6.46) 1(2034.9,-1561.7) 1(2034.9,-1561.7) 1(2034.9,-1520.7) 1(2034.9,-1520.7) 1(2035.17,144.16) 1(2035.17,230.43) 1(2035.17,230.43) 1(2042.54,2326.37) 1(2042.54,2326.37) 1(2042.54,2349.37) 1(2042.54,2422.37) 1(2043.17,2007.38) 1(2043.17,2007.38) 1(2043.17,2030.38) 1(2043.17,2103.38) 1(2045.99,-702.54) 1(2045.99,-702.54) 1(2045.99,-607.27) 1(2045.99,-607.27) 1(2046.42,2377.49) 1(2046.42,2418.49) 1(2047.42,2431.49) 1(2047.42,2431.49) 1(2047.42,2472.49) 1(2047.42,2472.49) 1(2048.05,2059.5) 1(2048.05,2100.5) 1(2057.9,-1561.7) 1(2057.9,-1520.7) 1(2104.64,-469.68) 1(2104.64,-389.68) 1(2104.64,-73.54) 1(2104.64,6.46) 1(2107.9,-1561.7) 1(2107.9,-1520.7) 1(2130.9,-1561.7) 1(2130.9,-1561.7) 1(2130.9,-1520.7) 1(2130.9,-1520.7) 1(2136.64,-73.54) 1(2136.64,-73.54) 1(2136.64,-33.54) 1(2136.64,-33.54) 1(2136.64,6.46) 1(2136.64,6.46) 1(2138.64,-469.68) 1(2138.64,-469.68) 1(2138.64,-469.54) 1(2138.64,-469.54) 1(2138.64,-429.68) 1(2138.64,-429.68) 1(2138.64,-429.54) 1(2138.64,-429.54) 1(2138.64,-389.68) 1(2138.64,-389.68) 1(2138.64,-389.54) 1(2138.64,-389.54) 1(2138.64,-73.54) 1(2138.64,-73.54) 1(2138.64,-33.54) 1(2138.64,-33.54) 1(2138.64,6.46) 1(2138.64,6.46) 1(2170.64,-73.54) 1(2170.64,6.46) 1(2172.64,-469.54) 1(2172.64,-389.54) 1(2182.55,2333) 1(2182.55,2333) 1(2182.55,2356) 1(2182.55,2406) 1(2182.55,2429) 1(2182.55,2429) 1(2185.55,1854) 1(2185.55,1854) 1(2185.55,1877) 1(2185.55,1927) 1(2185.55,1950) 1(2185.55,1950) 1(2188.29,-1013.95) 1(2188.29,-1013.95) 1(2188.29,-990.95) 1(2188.29,-940.95) 1(2188.29,-917.95) 1(2188.29,-917.95) 1(2208.55,2229.38) 1(2208.55,2229.38) 1(2208.55,2252.38) 1(2208.55,2302.38) 1(2208.55,2325.38) 1(2208.55,2325.38) 1(2223.55,2333) 1(2223.55,2333) 1(2223.55,2356) 1(2223.55,2406) 1(2223.55,2429) 1(2223.55,2429) 1(2226.55,1854) 1(2226.55,1854) 1(2226.55,1877) 1(2226.55,1927) 1(2226.55,1950) 1(2226.55,1950) 1(2229.29,-1013.95) 1(2229.29,-1013.95) 1(2229.29,-990.95) 1(2229.29,-940.95) 1(2229.29,-917.95) 1(2229.29,-917.95) 1(2232.04,143.45) 1(2232.04,143.45) 1(2232.04,332.43) 1(2232.04,332.43) 1(2232.04,178.89) 1(2232.04,297) 1(2238.15,-709.18) 1(2238.15,-709.18) 1(2238.15,-613.91) 1(2238.15,-613.91) 1(2249.55,2229.38) 1(2249.55,2229.38) 1(2249.55,2252.38) 1(2249.55,2302.38) 1(2249.55,2325.38) 1(2249.55,2325.38) 1(2250.64,-73.54) 1(2250.64,6.46) 1(2252.29,-1013.95) 1(2252.29,-1013.95) 1(2252.29,-990.95) 1(2252.29,-940.95) 1(2252.29,-917.95) 1(2252.29,-917.95) 1(2252.64,-469.54) 1(2252.64,-389.54) 1(2273.58,-709.18) 1(2273.58,-613.91) 1(2284.64,-73.54) 1(2284.64,-73.54) 1(2284.64,-33.54) 1(2284.64,-33.54) 1(2284.64,6.46) 1(2284.64,6.46) 1(2286.64,-469.54) 1(2286.64,-469.54) 1(2286.64,-429.54) 1(2286.64,-429.54) 1(2286.64,-389.54) 1(2286.64,-389.54) 1(2293.29,-1013.95) 1(2293.29,-1013.95) 1(2293.29,-990.95) 1(2293.29,-940.95) 1(2293.29,-917.95) 1(2293.29,-917.95) 1(2300.42,2276.49) 1(2300.42,2276.49) 1(2300.42,2286.49) 1(2300.42,2286.49) 1(2300.42,2327.49) 1(2300.42,2327.49) 1(2300.42,2235.49) 1(2300.42,2235.49) 1(2320.42,-2230.5) 1(2320.42,-2230.5) 1(2320.42,-2221.51) 1(2320.42,-2082.5) 1(2320.42,-2073.5) 1(2320.42,-2073.5) 1(2321.42,1911.55) 1(2321.42,1911.55) 1(2321.42,1952.55) 1(2321.42,1952.55) 1(2321.42,1860.49) 1(2321.42,1860.49) 1(2321.42,1901.49) 1(2321.42,1901.49) 1(2321.42,1969.53) 1(2321.42,1969.53) 1(2321.42,2010.53) 1(2321.42,2010.53) 1(2322.05,2019.5) 1(2322.05,2019.5) 1(2322.05,2060.5) 1(2322.05,2060.5) 1(2323.05,2069.5) 1(2323.05,2069.5) 1(2323.05,2110.5) 1(2323.05,2110.5) 1(2323.42,2235.49) 1(2323.42,2276.49) 1(2323.42,2286.49) 1(2323.42,2327.49) 1(2327.31,297) 1(2327.31,143.45) 1(2327.31,143.45) 1(2327.31,332.43) 1(2327.31,332.43) 1(2327.31,152.4) 1(2344.42,1911.55) 1(2344.42,1952.55) 1(2344.42,1969.53) 1(2344.42,2010.53) 1(2344.42,1860.49) 1(2344.42,1901.49) 1(2345.05,2019.5) 1(2345.05,2060.5) 1(2346.05,2069.5) 1(2346.05,2110.5) 1(2373.42,2276.49) 1(2373.42,2286.49) 1(2373.42,2327.49) 1(2373.42,2235.49) 1(2391.69,-709.18) 1(2391.69,-613.91) 1(2394.42,1911.55) 1(2394.42,1952.55) 1(2394.42,1860.49) 1(2394.42,1901.49) 1(2394.42,1969.53) 1(2394.42,2010.53) 1(2395.05,2019.5) 1(2395.05,2060.5) 1(2396.05,2069.5) 1(2396.05,2110.5) 1(2396.42,2235.49) 1(2396.42,2235.49) 1(2396.42,2276.49) 1(2396.42,2276.49) 1(2396.42,2286.49) 1(2396.42,2286.49) 1(2396.42,2327.49) 1(2396.42,2327.49) 1(2417.42,1911.55) 1(2417.42,1911.55) 1(2417.42,1952.55) 1(2417.42,1952.55) 1(2417.42,1969.53) 1(2417.42,1969.53) 1(2417.42,2010.53) 1(2417.42,2010.53) 1(2417.42,1860.49) 1(2417.42,1860.49) 1(2417.42,1901.49) 1(2417.42,1901.49) 1(2418.05,2019.5) 1(2418.05,2019.5) 1(2418.05,2060.5) 1(2418.05,2060.5) 1(2419.05,2069.5) 1(2419.05,2069.5) 1(2419.05,2110.5) 1(2419.05,2110.5) 1(2427.12,-709.18) 1(2427.12,-709.18) 1(2427.12,-613.91) 1(2427.12,-613.91) 1(2508.79,-2005.95) 1(2508.79,-2005.95) 1(2508.79,-1971.95) 1(2508.79,-1891.95) 1(2508.79,-1857.95) 1(2508.79,-1857.95) 1(2548.79,-2005.95) 1(2548.79,-2005.95) 1(2548.79,-1857.95) 1(2548.79,-1857.95) 1(2587.42,-2230.5) 1(2587.42,-2073.5) 1(2588.79,-2005.95) 1(2588.79,-2005.95) 1(2588.79,-1971.95) 1(2588.79,-1891.95) 1(2588.79,-1857.95) 1(2588.79,-1857.95) 1(2598.79,-2005.95) 1(2598.79,-2005.95) 1(2598.79,-1971.95) 1(2598.79,-1891.95) 1(2598.79,-1857.95) 1(2598.79,-1857.95) 1(2638.79,-2005.95) 1(2638.79,-2005.95) 1(2638.79,-1857.95) 1(2638.79,-1857.95) 1(2654.33,1803.25) 1(2654.33,1803.25) 1(2654.33,1840.85) 1(2654.33,1900.85) 1(2654.33,1938.45) 1(2654.33,1938.45) 1(2662.79,1752.44) 1(2662.79,1752.44) 1(2662.79,1793.44) 1(2662.79,1793.44) 1(2678.79,-2005.95) 1(2678.79,-2005.95) 1(2678.79,-1971.95) 1(2678.79,-1891.95) 1(2678.79,-1857.95) 1(2678.79,-1857.95) 1(2678.8,1090.42) 1(2678.8,1090.42) 1(2678.8,1144.89) 1(2678.8,1144.89) 1(2685.79,1752.44) 1(2685.79,1793.44) 1(2704.79,1090.42) 1(2704.79,1144.89) 1(2715.79,1550.55) 1(2715.79,1550.55) 1(2715.79,1591.55) 1(2715.79,1591.55) 1(2726.29,446.05) 1(2726.29,446.05) 1(2726.29,469.05) 1(2726.29,519.05) 1(2726.29,542.05) 1(2726.29,542.05) 1(2729.83,1803.25) 1(2729.83,1803.25) 1(2729.83,1938.45) 1(2729.83,1938.45) 1(2730.53,1803.95) 1(2730.53,1803.95) 1(2730.53,1840.85) 1(2730.53,1900.85) 1(2730.53,1937.76) 1(2730.53,1937.76) 1(2735.29,178.43) 1(2735.29,178.43) 1(2735.29,201.43) 1(2735.29,251.43) 1(2735.29,274.43) 1(2735.29,274.43) 1(2735.79,1752.44) 1(2735.79,1793.44) 1(2738.79,1550.55) 1(2738.79,1591.55) 1(2748.79,1802.05) 1(2748.79,1802.05) 1(2748.79,1836.05) 1(2748.79,1916.05) 1(2748.79,1950.05) 1(2748.79,1950.05) 1(2750.84,828.07) 1(2750.84,828.07) 1(2750.84,854.05) 1(2750.84,922.05) 1(2750.84,948.04) 1(2750.84,948.04) 1(2758.79,1752.44) 1(2758.79,1752.44) 1(2758.79,1793.44) 1(2758.79,1793.44) 1(2767.29,446.05) 1(2767.29,446.05) 1(2767.29,469.05) 1(2767.29,519.05) 1(2767.29,542.05) 1(2767.29,542.05) 1(2772.79,1090.42) 1(2772.79,1144.89) 1(2776.29,178.43) 1(2776.29,178.43) 1(2776.29,201.43) 1(2776.29,251.43) 1(2776.29,274.43) 1(2776.29,274.43) 1(2788.79,1550.55) 1(2788.79,1591.55) 1(2788.79,1802.05) 1(2788.79,1802.05) 1(2788.79,1950.05) 1(2788.79,1950.05) 1(2798.77,1090.42) 1(2798.77,1090.42) 1(2798.77,1144.89) 1(2798.77,1144.89) 1(2805.31,828.07) 1(2805.31,828.07) 1(2805.31,854.05) 1(2805.31,922.05) 1(2805.31,948.04) 1(2805.31,948.04) 1(2811.79,1550.55) 1(2811.79,1550.55) 1(2811.79,1591.55) 1(2811.79,1591.55) 1(2828.79,1802.05) 1(2828.79,1802.05) 1(2828.79,1836.05) 1(2828.79,1916.05) 1(2828.79,1950.05) 1(2828.79,1950.05) 1(2831.61,-1555.79) 1(2831.61,-1555.79) 1(2831.61,-1532.79) 1(2831.61,-1482.79) 1(2831.61,-1459.79) 1(2831.61,-1459.79) 1(2841.79,1983.55) 1(2841.79,1983.55) 1(2841.79,2024.55) 1(2841.79,2024.55) 1(2846.79,2055.55) 1(2846.79,2055.55) 1(2846.79,2096.55) 1(2846.79,2096.55) 1(2864.79,1983.55) 1(2864.79,2024.55) 1(2869.79,2055.55) 1(2869.79,2096.55) 1(2870.13,856.97) 1(2870.13,856.97) 1(2870.13,880.6) 1(2870.13,1156.19) 1(2870.13,1179.81) 1(2870.13,1179.81) 1(2870.13,1531.97) 1(2870.13,1531.97) 1(2870.13,1555.6) 1(2870.13,1831.19) 1(2870.13,1854.81) 1(2870.13,1854.81) 1(2872.61,-1555.79) 1(2872.61,-1555.79) 1(2872.61,-1532.79) 1(2872.61,-1482.79) 1(2872.61,-1459.79) 1(2872.61,-1459.79) 1(2903.29,-1556.95) 1(2903.29,-1556.95) 1(2903.29,-1533.95) 1(2903.29,-1483.95) 1(2903.29,-1460.95) 1(2903.29,-1460.95) 1(2914.79,1983.55) 1(2914.79,2024.55) 1(2919.79,2055.55) 1(2919.79,2096.55) 1(2933.13,856.97) 1(2933.13,1179.81) 1(2933.13,1531.97) 1(2933.13,1854.81) 1(2937.79,1983.55) 1(2937.79,1983.55) 1(2937.79,2024.55) 1(2937.79,2024.55) 1(2942.79,2055.55) 1(2942.79,2055.55) 1(2942.79,2096.55) 1(2942.79,2096.55) 1(2944.29,-1556.95) 1(2944.29,-1556.95) 1(2944.29,-1533.95) 1(2944.29,-1483.95) 1(2944.29,-1460.95) 1(2944.29,-1460.95)
  round 78.74 on Mech16: 1(375.42,-2149) 1(416.42,2585) 1(2851.42,2656)
  round 170 on Mech16: 1(412.32,-114.47) 1(415.42,2909) 1(2644.42,2929) 1(2652.32,-114.47)
  round 50 on Mech16: 1(430.67,-1075.21) 1(430.67,-282.69) 1(900.83,303.32) 1(900.83,1095.84)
